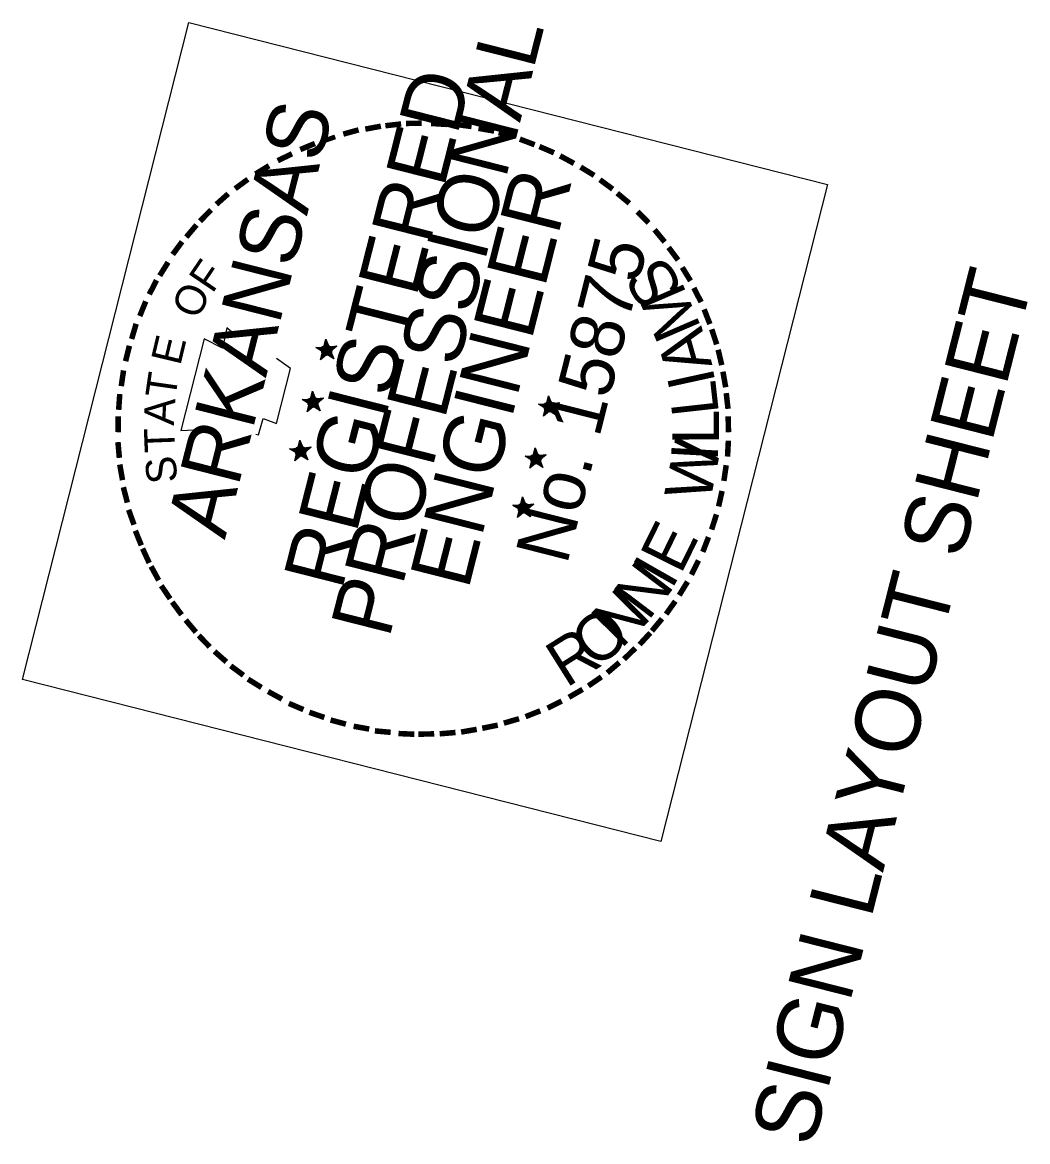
# Model space of a CAD drawing. Extents: x 670257 to 671518, y 737783 to 738188.
# Drawn here: x 670482.82 to 670491.1, y 738125.23 to 738134.44 of the extents above; entities that cross this region are included whole.
import ezdxf

# ---------------------------------------------------------------- set-up
doc = ezdxf.new("R2010")
doc.units = 0
for name, color, linetype in [('R_Border Notes', 7, 'Continuous'), ('R_Border PE', 7, 'Continuous'), ('R_Border Prem', 7, 'Continuous')]:
    doc.layers.add(name, color=color, linetype=linetype)

msp = doc.modelspace()

# ---------------------------------------------------------------- linework, layer by layer
at = {"layer": 'R_Border PE'}
for p, q in [((670485.3231, 738131.837), (670485.3089, 738131.7607)), ((670485.3231, 738131.837), (670485.3174, 738131.7637)), ((670485.3231, 738131.837), (670485.3222, 738131.7625)), ((670485.3231, 738131.837), (670485.3282, 738131.7455)), ((670485.3231, 738131.837), (670485.3314, 738131.7782)), ((670485.3231, 738131.837), (670485.3344, 738131.78)), ((670485.3231, 738131.837), (670485.3381, 738131.7842)), ((670485.4139, 738131.7779), (670485.3282, 738131.7455)), ((670485.4139, 738131.7779), (670485.3356, 738131.7642)), ((670485.4139, 738131.7779), (670485.3368, 738131.7691)), ((670485.4139, 738131.7779), (670485.3447, 738131.7593)), ((670485.4139, 738131.7779), (670485.3476, 738131.7405)), ((670485.4139, 738131.7779), (670485.3525, 738131.7496)), ((670485.4139, 738131.7779), (670485.3549, 738131.7387)), ((670485.241, 738131.7676), (670485.3059, 738131.7692)), ((670485.3282, 738131.7455), (670485.241, 738131.7676)), ((670485.241, 738131.7676), (670485.3047, 738131.7643)), ((670485.241, 738131.7676), (670485.3004, 738131.7577)), ((670485.241, 738131.7676), (670485.3004, 738131.7474)), ((670485.241, 738131.7676), (670485.2991, 738131.7425)), ((670485.241, 738131.7676), (670485.2955, 738131.7383)), ((670485.2801, 738131.6674), (670485.3282, 738131.7455)), ((670485.2801, 738131.6674), (670485.3033, 738131.7286)), ((670485.2801, 738131.6674), (670485.3076, 738131.7249)), ((670485.2801, 738131.6674), (670485.31, 738131.7243)), ((670485.2801, 738131.6674), (670485.3191, 738131.7194)), ((670485.2801, 738131.6674), (670485.3239, 738131.7182)), ((670485.2801, 738131.6674), (670485.3288, 738131.717)), ((670485.3874, 738131.6737), (670485.3269, 738131.72)), ((670485.3874, 738131.6737), (670485.3282, 738131.7455)), ((670485.3874, 738131.6737), (670485.3348, 738131.7206)), ((670485.3874, 738131.6737), (670485.3385, 738131.7248)), ((670485.3874, 738131.6737), (670485.3476, 738131.7405)), ((670485.3874, 738131.6737), (670485.3476, 738131.7302)), ((670485.3874, 738131.6737), (670485.3555, 738131.7411)), ((670485.2119, 738131.4087), (670485.1977, 738131.3324)), ((670485.2119, 738131.4087), (670485.2062, 738131.3354)), ((670485.2119, 738131.4087), (670485.211, 738131.3341)), ((670485.2119, 738131.4087), (670485.217, 738131.3171)), ((670485.2119, 738131.4087), (670485.2202, 738131.3499)), ((670485.2119, 738131.4087), (670485.2238, 738131.3541)), ((670485.2119, 738131.4087), (670485.2269, 738131.3559)), ((670485.1274, 738131.3399), (670485.1947, 738131.3409)), ((670485.217, 738131.3171), (670485.1274, 738131.3399)), ((670485.1274, 738131.3399), (670485.191, 738131.3366)), ((670485.1274, 738131.3399), (670485.1892, 738131.3294)), ((670485.1274, 738131.3399), (670485.1867, 738131.3197)), ((670485.1274, 738131.3399), (670485.1879, 738131.3142)), ((670485.1274, 738131.3399), (670485.1849, 738131.3124)), ((670485.1689, 738131.2391), (670485.217, 738131.3171)), ((670485.3033, 738131.352), (670485.217, 738131.3171)), ((670485.2768, 738131.2478), (670485.217, 738131.3171)), ((670485.3033, 738131.352), (670485.2232, 738131.3414)), ((670485.3033, 738131.352), (670485.2244, 738131.3359)), ((670485.3033, 738131.352), (670485.2335, 738131.331)), ((670485.3033, 738131.352), (670485.2364, 738131.3122)), ((670485.3033, 738131.352), (670485.2413, 738131.3213)), ((670485.3033, 738131.352), (670485.2437, 738131.3104)), ((670487.1569, 738131.3694), (670487.1433, 738131.2954)), ((670487.1569, 738131.3694), (670487.1518, 738131.2984)), ((670487.1569, 738131.3694), (670487.1567, 738131.2972)), ((670487.1569, 738131.3694), (670487.1627, 738131.2802)), ((670487.1569, 738131.3694), (670487.1652, 738131.3105)), ((670487.1569, 738131.3694), (670487.1713, 738131.3141)), ((670487.1569, 738131.3694), (670487.1743, 738131.3159)), ((670485.1689, 738131.2391), (670485.1897, 738131.3009)), ((670485.1689, 738131.2391), (670485.1945, 738131.2996)), ((670485.1689, 738131.2391), (670485.1988, 738131.296)), ((670485.1689, 738131.2391), (670485.2079, 738131.2911)), ((670485.1689, 738131.2391), (670485.2127, 738131.2899)), ((670485.1689, 738131.2391), (670485.2175, 738131.2886)), ((670485.2768, 738131.2478), (670485.2157, 738131.2917)), ((670485.2768, 738131.2478), (670485.2236, 738131.2923)), ((670485.2768, 738131.2478), (670485.2273, 738131.2965)), ((670485.2768, 738131.2478), (670485.2364, 738131.3122)), ((670485.2768, 738131.2478), (670485.2364, 738131.3019)), ((670485.2768, 738131.2478), (670485.2443, 738131.3128)), ((670487.1627, 738131.2802), (670487.0754, 738131.3023)), ((670487.0754, 738131.3023), (670487.1397, 738131.3015)), ((670487.0754, 738131.3023), (670487.1391, 738131.2991)), ((670487.0754, 738131.3023), (670487.1372, 738131.2918)), ((670487.0754, 738131.3023), (670487.1348, 738131.2821)), ((670487.0754, 738131.3023), (670487.1336, 738131.2773)), ((670487.0754, 738131.3023), (670487.1323, 738131.2724)), ((670487.1145, 738131.2021), (670487.1627, 738131.2802)), ((670487.1145, 738131.2021), (670487.1371, 738131.2609)), ((670487.1145, 738131.2021), (670487.142, 738131.2597)), ((670487.1145, 738131.2021), (670487.1462, 738131.256)), ((670487.1145, 738131.2021), (670487.1535, 738131.2542)), ((670487.1145, 738131.2021), (670487.1601, 738131.2499)), ((670487.1145, 738131.2021), (670487.165, 738131.2487)), ((670487.2218, 738131.2085), (670487.1608, 738131.2523)), ((670487.2483, 738131.3127), (670487.1627, 738131.2802)), ((670487.2218, 738131.2085), (670487.1627, 738131.2802)), ((670487.2483, 738131.3127), (670487.1694, 738131.2966)), ((670487.2483, 738131.3127), (670487.1706, 738131.3014)), ((670487.2218, 738131.2085), (670487.1711, 738131.2523)), ((670487.2218, 738131.2085), (670487.1753, 738131.2589)), ((670487.2483, 738131.3127), (670487.1809, 738131.2911)), ((670487.2218, 738131.2085), (670487.182, 738131.265)), ((670487.2483, 738131.3127), (670487.1839, 738131.2722)), ((670487.2218, 738131.2085), (670487.1839, 738131.2722)), ((670487.2483, 738131.3127), (670487.1863, 738131.2819)), ((670487.2218, 738131.2085), (670487.1893, 738131.2734)), ((670487.2483, 738131.3127), (670487.1911, 738131.2704)), ((670485.1093, 738131.004), (670485.0951, 738130.9277)), ((670485.1093, 738131.004), (670485.1035, 738130.9307)), ((670485.1093, 738131.004), (670485.1084, 738130.9295)), ((670485.1093, 738131.004), (670485.1144, 738130.9125)), ((670485.1093, 738131.004), (670485.1175, 738130.9452)), ((670485.1093, 738131.004), (670485.1212, 738130.9494)), ((670485.1093, 738131.004), (670485.1242, 738130.9512)), ((670485.2006, 738130.9473), (670485.1144, 738130.9125)), ((670485.2006, 738130.9473), (670485.1205, 738130.9367)), ((670485.2006, 738130.9473), (670485.1217, 738130.9312)), ((670485.2006, 738130.9473), (670485.1308, 738130.9264)), ((670485.2006, 738130.9473), (670485.1338, 738130.9075)), ((670485.2006, 738130.9473), (670485.1387, 738130.9166)), ((670485.2006, 738130.9473), (670485.1411, 738130.9057)), ((670485.0247, 738130.9352), (670485.092, 738130.9362)), ((670485.1144, 738130.9125), (670485.0247, 738130.9352)), ((670485.0247, 738130.9352), (670485.0884, 738130.932)), ((670485.0247, 738130.9352), (670485.0872, 738130.9271)), ((670485.0247, 738130.9352), (670485.0847, 738130.9174)), ((670485.0247, 738130.9352), (670485.0853, 738130.9095)), ((670485.0247, 738130.9352), (670485.0822, 738130.9077)), ((670485.0662, 738130.8344), (670485.1144, 738130.9125)), ((670485.0662, 738130.8344), (670485.0871, 738130.8962)), ((670485.0662, 738130.8344), (670485.0919, 738130.895)), ((670485.0662, 738130.8344), (670485.0961, 738130.8913)), ((670485.0662, 738130.8344), (670485.1058, 738130.8888)), ((670485.0662, 738130.8344), (670485.1101, 738130.8852)), ((670485.0662, 738130.8344), (670485.1149, 738130.884)), ((670485.1742, 738130.8431), (670485.1131, 738130.887)), ((670485.1742, 738130.8431), (670485.1144, 738130.9125)), ((670485.1742, 738130.8431), (670485.121, 738130.8876)), ((670485.1742, 738130.8431), (670485.1246, 738130.8918)), ((670485.1742, 738130.8431), (670485.1338, 738130.9075)), ((670485.1742, 738130.8431), (670485.1338, 738130.8972)), ((670485.1742, 738130.8431), (670485.1417, 738130.9081)), ((670487.0515, 738130.8519), (670486.9642, 738130.874)), ((670486.9642, 738130.874), (670487.0285, 738130.8732)), ((670486.9642, 738130.874), (670487.0279, 738130.8708)), ((670486.9642, 738130.874), (670487.026, 738130.8635)), ((670486.9642, 738130.874), (670487.0236, 738130.8538)), ((670486.9642, 738130.874), (670487.0223, 738130.849)), ((670486.9642, 738130.874), (670487.0187, 738130.8447)), ((670487.0457, 738130.9411), (670487.0321, 738130.8671)), ((670487.0457, 738130.9411), (670487.0406, 738130.8701)), ((670487.0457, 738130.9411), (670487.0455, 738130.8689)), ((670487.0457, 738130.9411), (670487.0515, 738130.8519)), ((670487.0457, 738130.9411), (670487.054, 738130.8822)), ((670487.0457, 738130.9411), (670487.0576, 738130.8864)), ((670487.0457, 738130.9411), (670487.0637, 738130.8901)), ((670487.1371, 738130.8843), (670487.0515, 738130.8519)), ((670487.1371, 738130.8843), (670487.0582, 738130.8682)), ((670487.1371, 738130.8843), (670487.06, 738130.8755)), ((670487.1371, 738130.8843), (670487.0679, 738130.8658)), ((670487.1371, 738130.8843), (670487.0733, 738130.8464)), ((670487.1371, 738130.8843), (670487.0751, 738130.8536)), ((670487.1371, 738130.8843), (670487.0775, 738130.8427)), ((670487.0033, 738130.7738), (670487.0515, 738130.8519)), ((670487.0033, 738130.7738), (670487.0259, 738130.8326)), ((670487.0033, 738130.7738), (670487.0308, 738130.8314)), ((670487.0033, 738130.7738), (670487.0332, 738130.8307)), ((670487.0033, 738130.7738), (670487.0423, 738130.8259)), ((670487.0033, 738130.7738), (670487.0471, 738130.8246)), ((670487.0033, 738130.7738), (670487.052, 738130.8234)), ((670487.1106, 738130.7801), (670487.0502, 738130.8264)), ((670487.1106, 738130.7801), (670487.0515, 738130.8519)), ((670487.1106, 738130.7801), (670487.0605, 738130.8264)), ((670487.1106, 738130.7801), (670487.0641, 738130.8306)), ((670487.1106, 738130.7801), (670487.0708, 738130.847)), ((670487.1106, 738130.7801), (670487.0708, 738130.8367)), ((670487.1106, 738130.7801), (670487.0781, 738130.8451)), ((670486.9437, 738130.5388), (670486.9295, 738130.4624)), ((670486.9437, 738130.5388), (670486.938, 738130.4654)), ((670486.9437, 738130.5388), (670486.9428, 738130.4642)), ((670486.9437, 738130.5388), (670486.9488, 738130.4472)), ((670486.9437, 738130.5388), (670486.9514, 738130.4775)), ((670486.9437, 738130.5388), (670486.955, 738130.4818)), ((670486.9437, 738130.5388), (670486.9611, 738130.4854)), ((670486.8616, 738130.4693), (670486.9265, 738130.4709)), ((670486.9488, 738130.4472), (670486.8616, 738130.4693)), ((670486.8616, 738130.4693), (670486.9252, 738130.4661)), ((670486.8616, 738130.4693), (670486.9234, 738130.4588)), ((670486.8616, 738130.4693), (670486.9209, 738130.4491)), ((670486.8616, 738130.4693), (670486.9197, 738130.4443)), ((670486.8616, 738130.4693), (670486.9161, 738130.44)), ((670486.9007, 738130.3692), (670486.9488, 738130.4472)), ((670486.9007, 738130.3692), (670486.9239, 738130.4303)), ((670486.9007, 738130.3692), (670486.9281, 738130.4267)), ((670486.9007, 738130.3692), (670486.9306, 738130.4261)), ((670486.9007, 738130.3692), (670486.9396, 738130.4212)), ((670486.9007, 738130.3692), (670486.9445, 738130.4199)), ((670486.9007, 738130.3692), (670486.9493, 738130.4187)), ((670487.008, 738130.3755), (670486.9475, 738130.4217)), ((670487.0344, 738130.4797), (670486.9488, 738130.4472)), ((670487.008, 738130.3755), (670486.9488, 738130.4472)), ((670487.0344, 738130.4797), (670486.9555, 738130.4636)), ((670487.0344, 738130.4797), (670486.9574, 738130.4708)), ((670487.008, 738130.3755), (670486.9578, 738130.4217)), ((670487.008, 738130.3755), (670486.9615, 738130.4259)), ((670487.0344, 738130.4797), (670486.9652, 738130.4611)), ((670487.008, 738130.3755), (670486.9682, 738130.4423)), ((670487.008, 738130.3755), (670486.9682, 738130.432)), ((670487.0344, 738130.4797), (670486.9706, 738130.4417)), ((670487.0344, 738130.4797), (670486.9725, 738130.4489)), ((670487.0344, 738130.4797), (670486.9749, 738130.438)), ((670487.008, 738130.3755), (670486.9755, 738130.4405))]:
    msp.add_line(p, q, dxfattribs=at)
for points in [[(670484.5677, 738131.879), (670484.5085, 738131.9302), (670484.4709, 738131.7617), (670484.3202, 738131.8386), (670484.1291, 738131.085)], [(670485.241, 738131.7676), (670485.4139, 738131.7779), (670485.2801, 738131.6674), (670485.3231, 738131.837), (670485.3874, 738131.6737), (670485.241, 738131.7676)], [(670484.7456, 738131.055), (670484.7674, 738131.0495), (670484.8067, 738131.1839), (670484.9175, 738131.1429), (670485.0324, 738131.5961), (670484.9163, 738131.6771)], [(670485.1274, 738131.3399), (670485.3033, 738131.352), (670485.1689, 738131.2391), (670485.2119, 738131.4087), (670485.2768, 738131.2478), (670485.1274, 738131.3399)], [(670487.0754, 738131.3023), (670487.2483, 738131.3127), (670487.1145, 738131.2021), (670487.1569, 738131.3694), (670487.2218, 738131.2085), (670487.0754, 738131.3023)], [(670484.1291, 738131.085), (670484.3462, 738131.097)], [(670485.0247, 738130.9352), (670485.2006, 738130.9473), (670485.0662, 738130.8344), (670485.1093, 738131.004), (670485.1742, 738130.8431), (670485.0247, 738130.9352)], [(670486.9642, 738130.874), (670487.1371, 738130.8843), (670487.0033, 738130.7738), (670487.0457, 738130.9411), (670487.1106, 738130.7801), (670486.9642, 738130.874)], [(670486.8616, 738130.4693), (670487.0344, 738130.4797), (670486.9007, 738130.3692), (670486.9437, 738130.5388), (670487.008, 738130.3755), (670486.8616, 738130.4693)]]:
    msp.add_lwpolyline(points, dxfattribs=at)
for centre, radius in [((670485.3288, 738131.7451), 0.0431), ((670485.3288, 738131.7451), 0.039), ((670485.3288, 738131.7451), 0.0361), ((670485.3288, 738131.7451), 0.0332), ((670485.3288, 738131.7451), 0.0289), ((670485.3288, 738131.7451), 0.0269), ((670485.3288, 738131.7451), 0.0248), ((670485.3288, 738131.7451), 0.0213), ((670485.3288, 738131.7451), 0.0187), ((670485.3288, 738131.7451), 0.0155), ((670485.3288, 738131.7451), 0.0124), ((670485.3288, 738131.7451), 0.00924), ((670485.3288, 738131.7451), 0.00741), ((670485.3288, 738131.7451), 0.0036), ((670485.2174, 738131.3176), 0.0431), ((670485.2174, 738131.3176), 0.039), ((670485.2174, 738131.3176), 0.0361), ((670485.2174, 738131.3176), 0.0332), ((670485.2174, 738131.3176), 0.0289), ((670485.2174, 738131.3176), 0.0269), ((670485.2174, 738131.3176), 0.0248), ((670485.2174, 738131.3176), 0.0213), ((670485.2174, 738131.3176), 0.0187), ((670485.2174, 738131.3176), 0.0155), ((670485.2174, 738131.3176), 0.0124), ((670485.2174, 738131.3176), 0.00924), ((670485.2174, 738131.3176), 0.00741), ((670485.2174, 738131.3176), 0.0036), ((670487.1637, 738131.2787), 0.0431), ((670487.1637, 738131.2787), 0.039), ((670487.1637, 738131.2787), 0.0361), ((670487.1637, 738131.2787), 0.0332), ((670487.1637, 738131.2787), 0.0289), ((670487.1637, 738131.2787), 0.0269), ((670487.1637, 738131.2787), 0.0248), ((670487.1637, 738131.2787), 0.0213), ((670487.1637, 738131.2787), 0.0187), ((670487.1637, 738131.2787), 0.0155), ((670487.1637, 738131.2787), 0.0124), ((670487.1637, 738131.2787), 0.00924), ((670487.1637, 738131.2787), 0.00741), ((670487.1637, 738131.2787), 0.0036), ((670485.1148, 738130.9131), 0.0431), ((670485.1148, 738130.9131), 0.039), ((670485.1148, 738130.9131), 0.0361), ((670485.1148, 738130.9131), 0.0332), ((670485.1148, 738130.9131), 0.0289), ((670485.1148, 738130.9131), 0.0269), ((670485.1148, 738130.9131), 0.0248), ((670485.1148, 738130.9131), 0.0213), ((670485.1148, 738130.9131), 0.0187), ((670485.1148, 738130.9131), 0.0155), ((670485.1148, 738130.9131), 0.0124), ((670485.1148, 738130.9131), 0.00924), ((670485.1148, 738130.9131), 0.00741), ((670485.1148, 738130.9131), 0.0036), ((670487.0523, 738130.8512), 0.0431), ((670487.0523, 738130.8512), 0.039), ((670487.0523, 738130.8512), 0.0361), ((670487.0523, 738130.8512), 0.0332), ((670487.0523, 738130.8512), 0.0289), ((670487.0523, 738130.8512), 0.0269), ((670487.0523, 738130.8512), 0.0248), ((670487.0523, 738130.8512), 0.0213), ((670487.0523, 738130.8512), 0.0187), ((670487.0523, 738130.8512), 0.0155), ((670487.0523, 738130.8512), 0.0124), ((670487.0523, 738130.8512), 0.00924), ((670487.0523, 738130.8512), 0.00741), ((670487.0523, 738130.8512), 0.0036), ((670486.9497, 738130.4467), 0.0431), ((670486.9497, 738130.4467), 0.039), ((670486.9497, 738130.4467), 0.0361), ((670486.9497, 738130.4467), 0.0332), ((670486.9497, 738130.4467), 0.0289), ((670486.9497, 738130.4467), 0.0269), ((670486.9497, 738130.4467), 0.0248), ((670486.9497, 738130.4467), 0.0213), ((670486.9497, 738130.4467), 0.0187), ((670486.9497, 738130.4467), 0.0155), ((670486.9497, 738130.4467), 0.0124), ((670486.9497, 738130.4467), 0.00924), ((670486.9497, 738130.4467), 0.00741), ((670486.9497, 738130.4467), 0.0036)]:
    msp.add_circle(centre, radius, dxfattribs=at)
at = {"layer": 'R_Border Prem'}
msp.add_lwpolyline([(670482.8233, 738129.0354), (670484.1951, 738134.4441), (670489.4534, 738133.1104), (670488.0817, 738127.7017)], close=True, dxfattribs=at)

# ---------------------------------------------------------------- texts
at = {"layer": 'R_Border Notes'}
msp.add_text('SIGN LAYOUT SHEET', height=0.533593, rotation=75.76855, dxfattribs=at).set_placement((670489.3352, 738125.1743))
at = {"layer": 'R_Border PE'}
for s, height, rotation, p in [('PROFESSIONAL', 0.499995, 75.76855, (670485.844, 738129.3656)), ('REGISTERED', 0.5, 75.76855, (670485.4543, 738129.7611)), ('ARKANSAS', 0.5, 75.76855, (670484.4904, 738130.1809)), ('-', 0.3999, 6.34138, (670485.8064, 738133.4373)), ('-', 0.4, 0.89181, (670485.961, 738133.4574)), ('-', 0.4, 356.31789, (670486.1551, 738133.4598)), ('-', 0.4, 352.36471, (670486.3497, 738133.4543)), ('-', 0.4, 15.4369, (670485.4848, 738133.3693)), ('-', 0.3999, 10.43135, (670485.6522, 738133.4094)), ('-', 0.4, 350.09866, (670486.5303, 738133.424)), ('-', 0.3999, 345.70922, (670486.6848, 738133.3925)), ('-', 0.3999, 22.42073, (670485.149, 738133.2456)), ('-', 0.35, 19.44384, (670485.3173, 738133.3293)), ('-', 0.3999, 339.28575, (670486.8435, 738133.3471)), ('-', 0.4, 336.76384, (670486.9991, 738133.2896)), ('-', 0.3999, 25.64828, (670484.9717, 738133.1564)), ('-', 0.3999, 331.53115, (670487.1572, 738133.2211)), ('-', 0.4, 31.34714, (670484.8034, 738133.0521)), ('-', 0.4, 328.63664, (670487.3206, 738133.1333)), ('-', 0.4, 36.29826, (670484.6477, 738132.9368)), ('ENGINEER', 0.5, 75.76855, (670486.4948, 738129.7654)), ('-', 0.4, 323.65722, (670487.4694, 738133.0388)), ('-', 0.3999, 41.63121, (670484.5061, 738132.8154)), ('-', 0.4, 320.38827, (670487.6055, 738132.9346)), ('-', 0.3999, 45.40945, (670484.3795, 738132.6825)), ('-', 0.4, 314.8398, (670487.7633, 738132.794)), ('-', 0.4, 49.88964, (670484.276, 738132.5591)), ('-', 0.4, 309.61379, (670487.8962, 738132.6571)), ('-', 0.4, 53.62364, (670484.1718, 738132.423)), ('No. 15875', 0.44, 75.76855, (670487.3079, 738129.9714)), ('-', 0.4, 307.02232, (670488.0079, 738132.5179)), ('-', 0.4, 58.10475, (670484.073, 738132.2572)), ('F', 0.2499, 55.83921, (670484.3876, 738132.2058)), ('S', 0.3849, 121.46196, (670488.2769, 738132.2463)), ('-', 0.3999, 301.53388, (670488.1141, 738132.3672)), ('-', 0.4, 62.97344, (670483.9955, 738132.1144)), ('O', 0.2499, 66.22005, (670484.2734, 738131.9898)), ('M', 0.3849, 113.32556, (670488.4178, 738131.9305)), ('-', 0.3999, 296.85364, (670488.2057, 738132.2098)), ('-', 0.4, 67.93028, (670483.9246, 738131.9467)), ('-', 0.3999, 291.50488, (670488.2858, 738132.0476)), ('-', 0.4, 73.51159, (670483.8646, 738131.7711)), ('A', 0.3849, 105.76014, (670488.5075, 738131.6216)), ('-', 0.4, 288.01764, (670488.3471, 738131.8928)), ('-', 0.3999, 75.95478, (670483.8173, 738131.5948)), ('E', 0.25, 76.60089, (670484.1236, 738131.6125)), ('-', 0.4, 283.12539, (670488.3981, 738131.738)), ('-', 0.3999, 81.66537, (670483.787, 738131.4039)), ('T', 0.25, 81.79131, (670484.0826, 738131.3392)), ('I', 0.3849, 102.33428, (670488.5345, 738131.4784)), ('-', 0.3999, 280.02017, (670488.437, 738131.5657)), ('L', 0.3849, 96.33904, (670488.5611, 738131.2249)), ('-', 0.4, 85.9879, (670483.7688, 738131.2202)), ('A', 0.25, 86.98173, (670484.0716, 738131.1228)), ('-', 0.4, 276.48697, (670488.4643, 738131.3989)), ('L', 0.3849, 90.3438, (670488.5611, 738130.97)), ('-', 0.3999, 89.3987, (670483.7657, 738131.0456)), ('-', 0.3999, 271.24284, (670488.4813, 738131.2217)), ('T', 0.2499, 92.17215, (670484.0812, 738130.9063)), ('-', 0.3999, 94.94463, (670483.7778, 738130.8491)), ('W', 0.3849, 78.78155, (670488.4861, 738130.4847)), ('-', 0.4, 267.05431, (670488.4849, 738131.0326)), ('S', 0.2499, 97.36257, (670484.1052, 738130.6655)), ('I', 0.3849, 86.91795, (670488.5491, 738130.8247)), ('-', 0.4, 100.07576, (670483.8045, 738130.6798)), ('-', 0.3999, 261.58522, (670488.4709, 738130.8452)), ('-', 0.4, 104.56037, (670483.8433, 738130.5075)), ('-', 0.4, 257.36031, (670488.4405, 738130.644)), ('-', 0.4, 109.83212, (670483.8961, 738130.3394)), ('-', 0.4, 252.28682, (670488.3999, 738130.4635)), ('E', 0.3849, 63.72208, (670488.2457, 738129.8928)), ('-', 0.3999, 112.00029, (670483.955, 738130.1749)), ('-', 0.4, 248.88401, (670488.3392, 738130.2854)), ('-', 0.3999, 114.71921, (670484.0182, 738130.0376)), ('I', 0.3849, 60.29623, (670488.1699, 738129.7683)), ('-', 0.3999, 118.7308, (670484.0929, 738129.9052)), ('N', 0.3849, 52.7308, (670487.9771, 738129.511)), ('-', 0.4, 243.32407, (670488.2652, 738130.1056)), ('-', 0.4, 238.56682, (670488.1822, 738129.941)), ('-', 0.4, 124.1916, (670484.1816, 738129.7666)), ('N', 0.3849, 45.16538, (670487.7521, 738129.2812)), ('-', 0.3999, 126.38273, (670484.2733, 738129.6402)), ('-', 0.4, 234.32977, (670488.0895, 738129.7891)), ('O', 0.3849, 38.88465, (670487.5436, 738129.1143)), ('-', 0.4, 130.00102, (670484.3862, 738129.5058)), ('-', 0.3999, 230.36875, (670487.9878, 738129.6524)), ('-', 0.4, 133.83918, (670484.4944, 738129.3933)), ('R', 0.3849, 32.17569, (670487.3022, 738128.9624)), ('-', 0.3999, 227.33894, (670487.8977, 738129.5411)), ('-', 0.4, 223.85834, (670487.7821, 738129.4209)), ('-', 0.3999, 138.6399, (670484.6232, 738129.2806)), ('-', 0.3999, 143.54282, (670484.755, 738129.1802)), ('-', 0.3999, 220.41489, (670487.658, 738129.3079)), ('-', 0.3999, 148.16302, (670484.8941, 738129.0881)), ('-', 0.4, 214.70237, (670487.5242, 738129.1974)), ('-', 0.4, 151.22951, (670485.0569, 738128.9978)), ('-', 0.4, 209.99236, (670487.3808, 738129.0997)), ('-', 0.3999, 156.96982, (670485.2204, 738128.9203)), ('-', 0.3999, 206.48667, (670487.218, 738129.0068)), ('-', 0.3999, 160.95489, (670485.3833, 738128.8609)), ('-', 0.4, 201.662, (670487.054, 738128.9298)), ('-', 0.4, 164.83079, (670485.5511, 738128.8106)), ('-', 0.3999, 169.96443, (670485.7304, 738128.7754)), ('-', 0.3999, 189.83287, (670486.5624, 738128.7811)), ('-', 0.3999, 191.4974, (670486.731, 738128.8157)), ('-', 0.4, 196.21567, (670486.8937, 738128.8673)), ('-', 0.3999, 174.71648, (670485.8947, 738128.7518)), ('-', 0.4, 177.4835, (670486.082, 738128.7379)), ('-', 0.4, 181.2264, (670486.2354, 738128.7428)), ('-', 0.3999, 184.85597, (670486.401, 738128.755))]:
    msp.add_text(s, height=height, rotation=rotation, dxfattribs=at).set_placement(p)

doc.saveas('drawing.dxf')
